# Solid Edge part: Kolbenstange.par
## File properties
Last saved by: ahadarics
Revision: 76
Dokumentum tartalom típus: 0
Sűrűség: 0,000 kg/m^3
Pontosság: 0,990
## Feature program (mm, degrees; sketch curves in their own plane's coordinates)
base feature "unnamed BaseFeature 1"
thread "unnamed Thread 1"
sketch for "unnamed Protrusion 1" plane through (0, 0, -39.5) normal (0, 0, -1) x-axis (0, -1, 0)
  circle centre (0, 0) radius 25
extrude "unnamed Protrusion 1" add finite 16 along -normal
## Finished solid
Body 1: solid body, 17 faces, 23 edges, 8 vertices.
  Faces by surface: plane 8, cylinder 4, torus 3, cone 2
  Edges by curve: circle 13, line 6, ellipse 2, intersection 2
Bounding box of the edges (mm; curved faces can reach further): 50.000 x 50.000 x 65.500, from (-25, -25, -39.5) to (25, 25, 26).
Cylindrical faces by radius (mm): R5 x1, R6 x1, R8 x1, R25 x1
Conical faces (half-angle, radius in mm at the cone's reference point): 20 deg R5.5 x1, 60 deg R5.6 x1
Toroidal faces (ring radius, tube radius in mm): R5.4 r0.4 x2, R6.3 r1.7 x1
Planar faces by outward normal: +x 1, +z 3, -x 1, -z 1, oblique 2
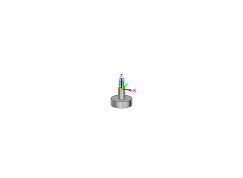
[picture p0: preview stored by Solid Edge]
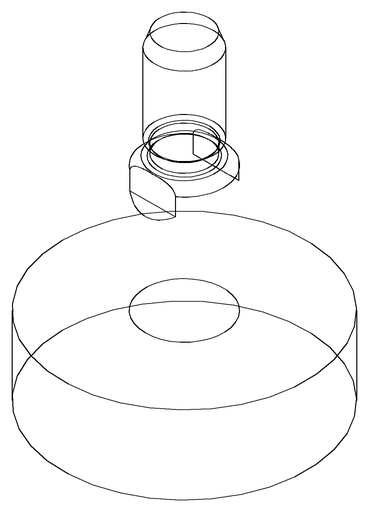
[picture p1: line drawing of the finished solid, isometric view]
